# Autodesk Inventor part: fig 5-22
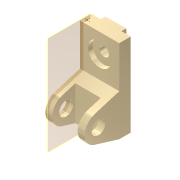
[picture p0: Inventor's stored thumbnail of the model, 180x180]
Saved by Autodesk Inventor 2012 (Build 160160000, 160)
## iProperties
Shininess: 65.0
Angle Display Precision: 2
Document Length Units: 11269
Document Angle Units: 11279
Document Time Units: 11290
Document Mass Units: 11283
Document Length Units Precision: 3
Document Angle Units Precision: 2
Compacted: False
Created: 2001-11
Part Number: fig 5-22
Document SubType Name: Modeling
Designer: Renu Muthoo
Density: 1 g/cm^3
Material: Default
Density: 0.0
Volumn: 0.0
Area: 0.0
PropertySet Name: Model Information
Control State: 0
Master: False
Checked Out: False
Author: Renu Muthoo
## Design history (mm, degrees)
node "Sketch1"
sketch "Sketch2"
  geometry: L1 (33.257, 104.664)-(33.257, -75.336); L2 (33.257, -75.336)-(8.257, -75.336); L3 (8.257, -75.336)-(-45.451, -59.045); L4 (-45.451, -1.628)-(8.257, 14.664); L5 (8.257, 14.664)-(8.257, 104.664); L6 (8.257, 104.664)-(33.257, 104.664); C1 r 15 at (-36.743, -30.336); A1 r 30 centre (-36.743, -30.336) between (-45.451, -1.628) and (-45.451, -59.045)
  constraints: 12 end point, 2 centre point, 2 equal length, 2 parallel, 2 point on circle, 2 tangent, 1 coincident, 1 perpendicular, 1 vertical
  dimensions: "d0" = 180 distance of L1.start L1.end; "d1" = 30 radius of A1; "d2" = 25 distance of L5.end L1.start; "d3" = 45 distance from line of L2 A1.centre; "d4" = 70 distance from line of L1 A1.centre; "d5" = 30 diameter of C1
extrude "Extrusion1" new body sketch "Sketch2" distance "d6" = 85; taper "d7" = 0 deg
workplane "Work Plane1"
sketch "Sketch3"
  geometry: L1 (15, 62.364)-(70, 62.364); L2 (70, 62.364)-(70, -52.386); L3 (70, -52.386)-(15, -52.386); L4 (15, -52.386)-(15, 62.364); L5 (0, -45)-(0, -28.708) reference
  constraints: 8 end point, 2 parallel, 1 horizontal, 1 perpendicular
  dimensions: "d8" = 55 distance of L1.start L1.end; "d9" = 15 distance between parallel lines of L5 L4
extrude "Extrusion2" cut sketch "Sketch3" distance "d10" = 50; taper "d11" = 0 deg
sketch "Sketch4"
  geometry: L1 (0, 25)-(85, 25) reference; L2 (0, 0)-(0, 25) reference; L3 (20, 25)-(65, 25); L4 (65, 25)-(65, 35); L5 (65, 35)-(20, 35); L6 (20, 35)-(20, 25)
  constraints: 8 end point, 2 parallel, 1 horizontal, 1 perpendicular, 1 point on line
  dimensions: "d12" = 45 distance of L4.end L5.end; "d13" = 10 distance of L3.end L4.end; "d14" = 20 distance between parallel lines of L2 L6
extrude "Extrusion3" join sketch "Sketch4" stored distance "d15" = 50; taper "d16" = 0 deg
sketch "Sketch5"
  geometry: L1 (85, 0)-(85, 90) reference; L2 (0, 90)-(85, 90) reference; 1 further point
  dimensions: "d17" = 42 distance from line of L2 point (42.5, 48); "d18" = 42.5 distance from line of L1 point (42.5, 48)
hole "Hole1" sketch "Sketch5" at (42.5, 48) diameter "d19" = 20; stored, may be unused: countersink angle "d23" = 82 deg, drill point angle "d25" = 118 deg; dims "d20" = 6, "d21" = 50, "d22" = 10, "d24" = 8
sketch "Sketch11"
  geometry: 1 further point
workplane "Work Plane17"
body "Solid1"
